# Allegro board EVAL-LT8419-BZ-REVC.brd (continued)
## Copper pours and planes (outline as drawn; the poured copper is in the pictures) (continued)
_N195 on TOP: 103.75,84.71 107.33,84.71 107.33,81.13 103.75,81.13
_N195 on TOP: 105.74,78.68 105.74,79.84 103.45,79.84 103.45,78.68
_N195 on TOP: 88.77,70.12 114.65,70.12 114.65,62.07 88.77,62.07
_N195 on TOP, BOTTOM: 107.09,76.98 107.09,77.68 103.49,77.68 103.49,76.98
_N195 on TOP, BOTTOM: 107.09,75.28 107.09,75.98 103.49,75.98 103.49,75.28
_N195 on TOP, BOTTOM: 98.1,77.83 98.1,78.53 94.5,78.53 94.5,77.83
_N195 on TOP, BOTTOM: 98.1,73.97 98.1,75.13 94.5,75.13 94.5,73.97
_N195 on TOP, BOTTOM: 98.1,76.13 98.1,76.83 94.5,76.83 94.5,76.13
_N195 on BOTTOM: 105.83,78.68 105.83,79.84 103.45,79.84 103.45,78.68
_N195 on BOTTOM: 114.65,70.17 114.65,62.07 88.77,62.07 88.77,65.99 98.59,65.99 99.14,66.53 99.14,67.41 99,67.54 98.43,67.54 98.27,67.38 98.27,67.02 98.21,66.97 88.77,66.97 88.77,70.17
_N195 on L2_PWR: 105.84,78.68 105.84,80.25 102.08,80.25 102.08,78.56 103.1,78.56 103.14,78.65 103.23,78.68
_N195 on L2_PWR: 102.44,80.25 103.1,80.25 103.1,71.01 114.65,71.01 114.65,62.07 88.77,62.07 88.77,71.01 95.91,71.01 95.91,73.97 98.61,73.97 98.61,78.25 100.79,78.25 100.79,84.09 102.44,84.09
_N195 on L2_PWR, L3_PWR, L4_PWR: 107.09,76.98 107.09,77.68 103.23,77.68 103.14,77.71 103.1,77.8 102.08,77.8 102.08,76.85 103.1,76.85 103.14,76.94 103.23,76.98
_N195 on L2_PWR, L3_PWR, L4_PWR: 107.09,75.28 107.09,75.98 103.23,75.98 103.14,76.01 103.1,76.1 102.08,76.1 102.08,75.15 103.1,75.15 103.14,75.24 103.23,75.28
_N195 on L2_PWR, L3_PWR, L4_PWR: 99.15,73.92 99.15,75.25 98.61,75.25 98.57,75.16 98.48,75.13 94.5,75.13 94.5,73.92
_N195 on L2_PWR, L3_PWR, L4_PWR: 99.19,76.95 98.61,76.95 98.57,76.86 98.48,76.83 94.5,76.83 94.5,76.13 98.48,76.13 98.57,76.09 98.61,76 99.19,76
_N195 on L2_PWR, L3_PWR, L4_PWR: 100.79,78.53 94.5,78.53 94.5,77.83 98.48,77.83 98.57,77.79 98.61,77.7 100.79,77.7
_N195 on L3_PWR: 105.74,78.68 105.74,80.25 102.08,80.25 102.08,78.56 103.1,78.56 103.14,78.65 103.23,78.68
_N195 on L3_PWR: 100.79,80.25 103.1,80.25 103.1,71.01 114.65,71.01 114.65,62.07 88.77,62.07 88.77,71.01 95.91,71.01 95.91,73.97 98.61,73.97 98.61,78.25 100.79,78.25
_N195 on L4_PWR: 100.79,79.84 103.1,79.84 103.1,71.01 114.65,71.01 114.65,62.07 88.77,62.07 88.77,71.01 95.91,71.01 95.91,73.97 98.61,73.97 98.61,78.25 100.79,78.25
_N195 on L4_PWR: 102.08,79.84 105.74,79.84 105.74,78.68 103.23,78.68 103.14,78.65 103.1,78.56 102.08,78.56
_N196 on BOTTOM: 88.77,61.56 88.77,54.92 114.65,54.92 114.65,61.56
_N196 on L2_PWR: 88.77,61.56 88.77,54.92 107.63,54.98 114.63,54.97 114.64,61.56
_N196 on L3_PWR: 88.77,61.56 88.77,54.92 114.65,54.92 114.65,61.56
_N196 on L4_PWR: 88.77,61.56 88.77,54.92 107.04,54.9 112.76,60.63 112.77,61.58
_N205 on TOP: 127.6,83.85 127.6,85.57 128.23,85.57 128.23,83.85
_N206 on TOP: 130.26,84.51 130.26,85.15 128.61,85.15 128.61,84.51
_N207 on TOP: 132.24,84.51 132.24,85.15 130.52,85.15 130.52,84.51
_N211 on TOP: 132.7,84.71 136.28,84.71 136.28,81.13 132.7,81.13
_N211 on TOP: 122.07,70.12 146.86,70.12 146.86,62.07 122.07,62.07
_N211 on TOP: 134.69,78.68 134.69,79.84 132.4,79.84 132.4,78.68
_N211 on TOP, BOTTOM: 127.05,77.83 127.05,78.53 123.45,78.53 123.45,77.83
_N211 on TOP, BOTTOM: 127.05,73.97 127.05,75.13 123.45,75.13 123.45,73.97
_N211 on TOP, BOTTOM: 127.05,76.13 127.05,76.83 123.45,76.83 123.45,76.13
_N211 on TOP, BOTTOM: 136.04,76.98 136.04,77.68 132.44,77.68 132.44,76.98
_N211 on TOP, BOTTOM: 136.04,75.28 136.04,75.98 132.44,75.98 132.44,75.28
_N211 on BOTTOM: 134.76,78.68 134.76,79.84 132.4,79.84 132.4,78.68
_N211 on BOTTOM: 143.6,70.17 143.6,62.07 122.07,62.07 122.07,65.69 130.83,65.69 131.26,66.11 131.26,67.28 131.15,67.39 130.59,67.39 130.42,67.23 130.42,66.81 130.27,66.66 122.07,66.66 122.07,70.17
_N211 on L2_PWR: 131.39,80.25 132.05,80.25 132.05,71.01 146.75,71.01 146.75,62.07 122.07,62.07 122.07,71.01 124.86,71.01 124.86,73.97 127.56,73.97 127.56,78.25 129.74,78.25 129.74,84.09 131.39,84.09
_N211 on L2_PWR: 134.77,78.68 134.77,80.25 131.03,80.25 131.03,78.56 132.05,78.56 132.09,78.65 132.18,78.68
_N211 on L2_PWR, L3_PWR, L4_PWR: 136.04,75.28 136.04,75.98 132.18,75.98 132.09,76.01 132.05,76.1 131.03,76.1 131.03,75.15 132.05,75.15 132.09,75.24 132.18,75.28
_N211 on L2_PWR, L3_PWR, L4_PWR: 129.74,78.53 123.45,78.53 123.45,77.83 127.43,77.83 127.52,77.79 127.56,77.7 129.74,77.7
_N211 on L2_PWR, L3_PWR, L4_PWR: 128.14,76.95 127.56,76.95 127.52,76.86 127.43,76.83 123.45,76.83 123.45,76.13 127.43,76.13 127.52,76.09 127.56,76 128.14,76
_N211 on L2_PWR, L3_PWR, L4_PWR: 128.11,73.92 128.11,75.25 127.56,75.25 127.52,75.16 127.43,75.13 123.45,75.13 123.45,73.92
_N211 on L2_PWR, L3_PWR, L4_PWR: 136.04,76.98 136.04,77.68 132.18,77.68 132.09,77.71 132.05,77.8 131.03,77.8 131.03,76.85 132.05,76.85 132.09,76.94 132.18,76.98
_N211 on L3_PWR: 134.69,78.68 134.69,80.25 131.03,80.25 131.03,78.56 132.05,78.56 132.09,78.65 132.18,78.68
_N211 on L3_PWR: 129.74,80.25 132.05,80.25 132.05,71.01 146.75,71.01 146.75,62.07 122.07,62.07 122.07,71.01 124.86,71.01 124.86,73.97 127.56,73.97 127.56,78.25 129.74,78.25
_N211 on L4_PWR: 131.03,79.84 134.69,79.84 134.69,78.68 132.18,78.68 132.09,78.65 132.05,78.56 131.03,78.56
_N211 on L4_PWR: 129.74,79.84 132.05,79.84 132.05,71.01 146.75,71.01 146.75,62.07 122.07,62.07 122.07,71.01 124.86,71.01 124.86,73.97 127.56,73.97 127.56,78.25 129.74,78.25
_N212 on BOTTOM: 122.07,61.56 122.07,54.92 143.6,54.92 143.6,61.56
_N212 on L2_PWR, L3_PWR: 122.07,61.56 122.07,54.92 146.65,54.92 146.65,61.56
_N212 on L4_PWR: 122.18,61.56 122.19,60.58 129.57,54.89 146.75,54.92 146.75,61.56
_N213 on TOP: 163.16,83.85 163.16,85.57 163.8,85.57 163.8,83.85
_N214 on TOP: 165.83,84.51 165.83,85.15 164.18,85.15 164.18,84.51
_N215 on TOP: 167.81,84.51 167.81,85.15 166.08,85.15 166.08,84.51
_N219 on TOP: 170.26,78.68 170.26,79.84 167.97,79.84 167.97,78.68
_N219 on TOP: 168.27,84.71 171.85,84.71 171.85,81.13 168.27,81.13
_N219 on TOP: 157.64,70.12 179.24,70.12 179.24,62.07 157.64,62.07
_N219 on TOP, BOTTOM: 162.62,73.97 162.62,75.13 159.02,75.13 159.02,73.97
_N219 on TOP, BOTTOM: 162.62,76.13 162.62,76.83 159.02,76.83 159.02,76.13
_N219 on TOP, BOTTOM: 171.6,75.28 171.6,75.98 168,75.98 168,75.28
_N219 on TOP, BOTTOM: 162.62,77.83 162.62,78.53 159.02,78.53 159.02,77.83
_N219 on TOP, BOTTOM: 171.6,76.98 171.6,77.68 168,77.68 168,76.98
_N219 on BOTTOM: 179.16,70.17 179.16,62.07 157.64,62.07 157.64,65.69 165.49,65.69 165.8,66 165.8,67.47 165.64,67.64 165.09,67.64 164.86,67.41 164.86,66.72 164.75,66.62 157.64,66.62 157.64,70.17
_N219 on BOTTOM: 170.35,78.68 170.35,79.84 167.97,79.84 167.97,78.68
_N219 on L2_PWR: 170.38,78.68 170.38,80.25 166.59,80.25 166.59,78.56 167.62,78.56 167.66,78.65 167.75,78.68
_N219 on L2_PWR: 166.95,80.25 167.62,80.25 167.62,71.01 179.16,71.01 179.16,62.07 157.64,62.07 157.64,71.01 160.43,71.01 160.43,73.97 163.12,73.97 163.12,78.25 165.31,78.25 165.31,84.09 166.95,84.09
_N219 on L2_PWR, L3_PWR, L4_PWR: 171.6,75.28 171.6,75.98 167.75,75.98 167.66,76.01 167.62,76.1 166.59,76.1 166.59,75.15 167.62,75.15 167.66,75.24 167.75,75.28
_N219 on L2_PWR, L3_PWR, L4_PWR: 163.71,76.95 163.12,76.95 163.09,76.86 163,76.83 159.02,76.83 159.02,76.13 163,76.13 163.09,76.09 163.12,76 163.71,76
_N219 on L2_PWR, L3_PWR, L4_PWR: 165.31,78.53 159.02,78.53 159.02,77.83 163,77.83 163.09,77.79 163.12,77.7 165.31,77.7
_N219 on L2_PWR, L3_PWR, L4_PWR: 171.6,76.98 171.6,77.68 167.75,77.68 167.66,77.71 167.62,77.8 166.59,77.8 166.59,76.85 167.62,76.85 167.66,76.94 167.75,76.98
_N219 on L2_PWR, L3_PWR, L4_PWR: 163.67,73.92 163.67,75.25 163.12,75.25 163.09,75.16 163,75.13 159.02,75.13 159.02,73.92
_N219 on L3_PWR: 170.26,78.68 170.26,80.25 166.59,80.25 166.59,78.56 167.62,78.56 167.66,78.65 167.75,78.68
_N219 on L3_PWR: 165.31,80.25 167.62,80.25 167.62,71.01 179.16,71.01 179.16,62.07 157.64,62.07 157.64,71.01 160.43,71.01 160.43,73.97 163.12,73.97 163.12,78.25 165.31,78.25
_N219 on L4_PWR: 165.31,79.84 167.62,79.84 167.62,71.01 179.16,71.01 179.16,62.07 157.64,62.07 157.64,71.01 160.43,71.01 160.43,73.97 163.12,73.97 163.12,78.25 165.31,78.25
_N219 on L4_PWR: 166.59,79.84 170.26,79.84 170.26,78.68 167.75,78.68 167.66,78.65 167.62,78.56 166.59,78.56
_N220 on BOTTOM: 157.64,61.56 157.64,54.92 179.16,54.92 179.16,61.56
_N220 on L2_PWR, L3_PWR, L4_PWR: 157.64,61.56 157.64,54.92 179.16,54.92 179.16,61.56
_N221 on TOP: 192.11,83.85 192.11,85.57 192.75,85.57 192.75,83.85
_N222 on TOP: 194.78,84.51 194.78,85.15 193.13,85.15 193.13,84.51
_N223 on TOP: 196.76,84.51 196.76,85.15 195.03,85.15 195.03,84.51
_N227 on TOP: 197.22,84.71 200.8,84.71 200.8,81.13 197.22,81.13
_N227 on TOP: 199.21,78.68 199.21,79.84 196.92,79.84 196.92,78.68
_N227 on TOP: 186.59,70.12 208.19,70.12 208.19,62.07 186.59,62.07
_N227 on TOP, BOTTOM: 200.55,76.98 200.55,77.68 196.96,77.68 196.96,76.98
_N227 on TOP, BOTTOM: 191.57,76.13 191.57,76.83 187.97,76.83 187.97,76.13
_N227 on TOP, BOTTOM: 200.55,75.28 200.55,75.98 196.96,75.98 196.96,75.28
_N227 on TOP, BOTTOM: 191.57,77.83 191.57,78.53 187.97,78.53 187.97,77.83
_N227 on TOP, BOTTOM: 191.57,73.97 191.57,75.13 187.97,75.13 187.97,73.97
_N227 on BOTTOM: 208.11,70.17 208.11,62.07 186.59,62.07 186.59,66 195.55,66 195.87,66.33 195.87,67.05 195.77,67.16 195.12,67.16 195.02,67.05 195.02,67.05 194.94,66.97 186.59,66.97 186.59,70.17
_N227 on BOTTOM: 199.28,78.68 199.28,79.84 196.92,79.84 196.92,78.68
_N227 on L2_PWR: 199.31,78.68 199.31,80.25 195.54,80.25 195.54,78.56 196.57,78.56 196.61,78.65 196.7,78.68
_N227 on L2_PWR: 195.9,80.25 196.57,80.25 196.57,71.01 208.11,71.01 208.11,62.07 186.59,62.07 186.59,71.01 189.38,71.01 189.38,73.97 192.07,73.97 192.07,78.25 194.26,78.25 194.26,84.09 195.9,84.09
_N227 on L2_PWR, L3_PWR, L4_PWR: 192.66,76.95 192.07,76.95 192.04,76.86 191.95,76.83 187.97,76.83 187.97,76.13 191.95,76.13 192.04,76.09 192.07,76 192.66,76
_N227 on L2_PWR, L3_PWR, L4_PWR: 200.55,76.98 200.55,77.68 196.7,77.68 196.61,77.71 196.57,77.8 195.54,77.8 195.54,76.85 196.57,76.85 196.61,76.94 196.7,76.98
_N227 on L2_PWR, L3_PWR, L4_PWR: 192.62,73.92 192.62,75.25 192.07,75.25 192.04,75.16 191.95,75.13 187.97,75.13 187.97,73.92
_N227 on L2_PWR, L3_PWR, L4_PWR: 194.26,78.53 187.97,78.53 187.97,77.83 191.95,77.83 192.04,77.79 192.07,77.7 194.26,77.7
_N227 on L2_PWR, L3_PWR, L4_PWR: 200.55,75.28 200.55,75.98 196.7,75.98 196.61,76.01 196.57,76.1 195.54,76.1 195.54,75.15 196.57,75.15 196.61,75.24 196.7,75.28
_N227 on L3_PWR: 194.26,80.25 196.57,80.25 196.57,71.01 208.11,71.01 208.11,62.07 186.59,62.07 186.59,71.01 189.38,71.01 189.38,73.97 192.07,73.97 192.07,78.25 194.26,78.25
_N227 on L3_PWR: 199.21,78.68 199.21,80.25 195.54,80.25 195.54,78.56 196.57,78.56 196.61,78.65 196.7,78.68
_N227 on L4_PWR: 194.26,79.84 196.57,79.84 196.57,71.01 208.11,71.01 208.11,62.07 186.59,62.07 186.59,71.01 189.38,71.01 189.38,73.97 192.07,73.97 192.07,78.25 194.26,78.25
_N227 on L4_PWR: 195.54,79.84 199.21,79.84 199.21,78.68 196.7,78.68 196.61,78.65 196.57,78.56 195.54,78.56
_N228 on BOTTOM: 186.59,61.56 186.59,54.92 208.11,54.92 208.11,61.56
_N228 on L2_PWR, L3_PWR, L4_PWR: 186.59,61.56 186.59,54.92 208.11,54.92 208.11,61.56
_N375 on TOP: 42.66,78.68 42.66,79.84 41.51,79.84 41.51,78.68
_N376 on TOP: 33.67,78.81 33.67,79.96 32.52,79.96 32.52,78.81
_N377 on TOP: 71.61,78.68 71.61,79.84 70.46,79.84 70.46,78.68
_N378 on TOP: 62.62,78.81 62.62,79.96 61.47,79.96 61.47,78.81
_N379 on TOP: 107.17,78.68 107.17,79.84 106.02,79.84 106.02,78.68
_N380 on TOP: 98.19,78.81 98.19,79.96 97.04,79.96 97.04,78.81
_N381 on TOP: 136.13,78.68 136.13,79.84 134.98,79.84 134.98,78.68
_N382 on TOP: 127.14,78.81 127.14,79.96 125.99,79.96 125.99,78.81
_N383 on TOP: 171.69,78.68 171.69,79.84 170.54,79.84 170.54,78.68
_N384 on TOP: 162.7,78.81 162.7,79.96 161.55,79.96 161.55,78.81
_N385 on TOP: 200.64,78.68 200.64,79.84 199.49,79.84 199.49,78.68
_N386 on TOP: 191.65,78.81 191.65,79.96 190.5,79.96 190.5,78.81
CSB on BOTTOM: 3.49,15.56 3.49,14.03 4.48,14.03 4.48,15.56
DRVCC on TOP: 99.68,82.86 99.68,83.44 99.02,83.44 98.87,83.59 98.39,83.59 98.28,83.7 98.28,84.58 97.1,84.58 97.1,82.65 98.63,82.65 98.84,82.86
DRVCC on TOP: 128.63,82.86 128.63,83.44 127.97,83.44 127.82,83.59 127.34,83.59 127.23,83.7 127.23,84.58 126.05,84.58 126.05,82.65 127.59,82.65 127.79,82.86
DRVCC on TOP: 35.16,82.86 35.16,83.44 34.5,83.44 34.35,83.59 33.87,83.59 33.76,83.7 33.76,84.58 32.58,84.58 32.58,82.65 34.12,82.65 34.33,82.86
DRVCC on TOP: 164.19,82.86 164.19,83.44 163.53,83.44 163.38,83.59 162.91,83.59 162.8,83.7 162.8,84.58 161.61,84.58 161.61,82.65 163.15,82.65 163.36,82.86
DRVCC on TOP: 193.14,82.86 193.14,83.44 192.48,83.44 192.34,83.59 191.86,83.59 191.75,83.7 191.75,84.58 190.57,84.58 190.57,82.65 192.1,82.65 192.31,82.86
DRVCC on TOP: 105.16,33.6 105.16,34.77 106.9,34.77 106.9,33.6
DRVCC on TOP: 64.11,82.86 64.11,83.44 63.45,83.44 63.3,83.59 62.82,83.59 62.71,83.7 62.71,84.58 61.53,84.58 61.53,82.65 63.07,82.65 63.28,82.86
DRVCC on L7_SIG: 190.87,80.84 190.87,84.25 190.87,84.25 32.54,84.25 32.54,80.84
PGOOD on TOP: 108.64,46.54 108.64,47.33 107.23,47.33 107.23,46.54
PWMEN on L7_SIG: 196.54,84.76 196.54,87.3 38.26,87.3 38.26,84.76
SAC1 on TOP: 122.15,46.54 122.15,48.57 121.69,49.03 121.69,49.09 121.25,49.53 120.4,49.53 120.37,49.56 120.37,50.2 120.46,50.29 121.49,50.29 121.7,50.08 121.7,50.07 123.09,50.07 123.09,46.54
SAC2 on TOP: 114.53,46.54 114.53,50.07 115.93,50.07 116.12,50.27 117.13,50.27 117.26,50.13 117.26,49.59 117.17,49.49 116.38,49.49 115.93,49.04 115.93,49.03 115.47,48.57 115.47,46.54
SAC3 on TOP: 113.34,46.54 113.34,48.57 112.88,49.03 112.88,50.07 112.89,50.07 112.86,50.1 112.86,50.64 112.26,51.23 110.99,51.23 110.99,51.97 111.02,52 112.52,52 114.28,50.24 114.28,46.54
SAC4 on TOP: 114.91,30.14 114.91,28.11 114.46,27.65 114.46,26.61 114.5,26.61 114.48,26.58 114.48,26.21 113.97,25.7 112.66,25.7 112.51,25.55 112.51,24.76 112.62,24.65 115.09,24.65 115.85,25.42 115.85,30.14
SAC5 on TOP: 116.11,30.14 116.11,26.61 116.24,26.48 118.78,26.48 118.81,26.51 118.81,27.22 117.94,27.22 117.05,28.11 117.05,30.14
SAC6 on TOP: 123.73,30.14 123.73,28.11 122.81,27.19 122.71,27.19 122.7,27.2 121.93,27.2 121.9,27.18 121.9,26.43 121.91,26.43 122.91,26.43 123.09,26.61 124.67,26.61 124.67,30.14
SCL on BOTTOM: 5.06,15.56 5.06,14.03 6.05,14.03 6.05,15.56
SDA on BOTTOM: 8.2,15.56 8.2,14.03 9.19,14.03 9.19,15.56
SDO on BOTTOM: 6.63,15.56 6.63,14.03 7.62,14.03 7.62,15.56
SN1 on TOP: 130.4,28.94 130.4,27.76 131.39,27.76 131.39,28.94
SN1 on TOP: 124.23,44.48 124.23,46.09 125.01,46.09 125.01,44.48
SN1 on TOP: 116.13,46.54 116.13,48.78 116.44,49.08 118.31,49.08 118.31,48.14 117.32,48.14 117.07,47.89 117.07,46.54
SN1 on TOP: 123.07,30.14 123.07,27.91 122.76,27.6 120.91,27.6 120.91,28.54 121.9,28.54 122.13,28.77 122.13,30.14
SN1 on TOP: 20.39,1.27 20.39,16.37 115.01,16.37 115.01,1.27
SN1 on TOP: 117.71,30.14 117.71,27.91 118.01,27.6 119.89,27.6 119.89,28.54 118.9,28.54 118.65,28.79 118.65,30.14
SN1 on TOP: 101.91,38.95 101.91,40.36 102.9,40.36 103.29,39.96 104.04,39.96 104.04,38.95
SN1 on TOP: 121.49,46.54 121.49,48.78 121.18,49.08 119.33,49.08 119.33,48.14 120.32,48.14 120.55,47.92 120.55,46.54
SN1 on TOP: 114.25,30.14 114.25,27.91 113.95,27.6 112.07,27.6 112.07,28.54 113.06,28.54 113.31,28.79 113.31,30.14
SN1 on TOP: 112.68,46.54 112.68,48.78 112.37,49.08 110.49,49.08 110.49,48.14 111.48,48.14 111.74,47.89 111.74,46.54
SN1 on BOTTOM: 186.59,54.41 201.93,54.41 201.93,27.95 202.06,27.95 202.06,17.03 115.36,17.03 115.36,2.03 20.78,2.03 20.78,27.95 28.61,27.95 28.61,54.41 43.95,54.41 43.95,31.56 57.56,31.56 57.56,54.41 72.9,54.41 72.9,31.91 88.77,31.91 88.77,54.41 104.11,54.41 104.11,27.95 112.09,27.95 112.24,27.8 121.85,27.8 121.97,27.92 121.97,27.95 126.43,27.95 126.43,54.41 141.77,54.41 141.77,31.74 157.64,31.74 157.64,54.41 172.98,54.41 172.98,31.74 186.59,31.74
SN1 on BOTTOM: 217.87,72.3 217.87,73.7 218.66,73.7 218.66,72.3
SN1 on L2_PWR: 186.59,54.41 201.93,54.41 201.93,16.54 115.26,16.54 115.26,1.27 20.78,1.27 20.78,27.95 28.61,27.95 28.61,54.41 43.95,54.41 43.95,31.38 57.56,31.38 57.56,54.41 72.9,54.41 72.9,31.52 88.77,31.52 88.77,54.41 109.65,54.41 109.65,54.44 124.56,54.44 124.56,54.41 141.77,54.41 141.77,31.73 157.64,31.73 157.64,54.41 172.98,54.41 172.98,32.29 186.59,32.29
SN1 on L3_PWR: 186.59,54.41 201.93,54.41 201.93,17.21 115.31,17.21 115.31,2.03 20.78,2.03 20.78,27.95 28.61,27.95 28.61,54.41 43.95,54.41 43.95,32.15 57.56,32.15 57.56,54.41 72.9,54.41 72.9,32.15 88.77,32.15 88.77,54.41 109.65,54.41 109.65,54.3 124.56,54.3 124.56,54.41 141.77,54.41 141.77,32.36 157.64,32.36 157.64,54.41 172.98,54.41 172.98,32.22 186.59,32.22
SN1 on L4_PWR: 22.48,1.27 22.48,17.21 114.3,17.21 114.3,1.27
SN1 on L5_GND: 19.02,1.27 19.02,17.28 113.96,17.28 113.96,1.27
SN1 on L6_SIG: 20.71,1.27 20.71,16.93 113.61,16.93 113.61,1.27
VHIGH on TOP: 36.28,138.43 114.05,138.43 114.05,123.79 208.11,123.79 208.11,70.63 194.26,70.63 194.26,83.38 196.28,83.38 196.28,86.57 194.26,88.59 194.26,105.28 179.16,105.28 179.16,70.63 165.31,70.63 165.31,83.38 167.33,83.38 167.33,86.57 165.31,88.59 165.31,106.29 165.22,106.38 146.85,106.38 146.72,106.25 146.72,105.87 146.72,105.28 146.68,105.28 146.68,70.63 129.74,70.63 129.74,83.38 131.76,83.38 131.76,86.57 129.74,88.59 129.74,105.46 114.65,105.46 114.65,70.63 100.79,70.63 100.79,83.38 102.81,83.38 102.81,86.57 100.79,88.59 100.79,105.45 81.74,105.45 81.74,70.63 65.23,70.63 65.23,83.38 67.25,83.38 67.25,86.57 65.23,88.59 65.23,104.94 50.13,104.94 50.13,70.63 36.28,70.63 36.28,83.38 38.29,83.38 38.29,86.57 36.28,88.59 ; 6 cut-outs
VHIGH on TOP: 127.83,45.61 127.83,47.01 129.49,47.01 129.49,45.61
VHIGH on TOP: 127.78,39.87 127.78,41.26 131.69,41.26 131.69,40.36 129.98,40.36 129.49,39.87
VHIGH on TOP: 102.77,28.24 102.77,26.58 104.52,26.58 104.52,28.24
VHIGH on BOTTOM: 217.54,78.09 217.54,80 218.58,80 218.58,78.09
VHIGH on BOTTOM: 36.28,138.43 36.28,70.68 50.13,70.68 50.13,107.35 65.23,107.35 65.23,70.68 82.09,70.68 82.09,106.83 100.79,106.83 100.79,70.68 114.65,70.68 114.65,106.32 129.74,106.32 129.74,70.68 143.6,70.68 143.61,70.67 146.68,70.7 146.68,105.8 165.31,105.8 165.31,70.68 179.16,70.68 179.16,106.06 194.26,106.06 194.26,70.68 208.11,70.68 208.11,123.74 114.05,123.74 114.05,138.43
VHIGH on L2_PWR: 36.28,138.43 36.28,79.77 36.27,79.77 36.27,71.52 50.13,71.52 50.13,106.12 65.23,106.12 65.23,70.63 82.13,70.63 82.13,106.19 100.79,106.19 100.79,70.63 114.65,70.63 114.65,106.4 129.74,106.4 129.74,70.63 143.6,70.63 143.64,70.59 146.68,70.59 146.68,106.23 146.85,106.4 165.31,106.4 165.31,70.63 179.16,70.63 179.16,106.12 194.26,106.12 194.26,70.63 208.11,70.63 208.11,123.79 114.05,123.79 114.05,138.43
VHIGH on L3_PWR: 36.28,138.43 36.28,70.63 50.13,70.63 50.13,106.05 65.23,106.05 65.23,70.63 78.19,70.63 78.19,70.64 79.05,71.5 79.58,71.5 79.59,71.49 79.58,71.49 79.58,70.63 82.06,70.63 82.06,106.33 100.79,106.33 100.79,70.63 114.65,70.63 114.65,106.05 129.74,106.05 129.74,70.63 143.6,70.63 143.6,71.54 143.62,71.52 146.69,71.52 146.69,106.12 165.31,106.12 165.31,70.63 179.16,70.63 179.16,105.84 194.26,105.84 194.26,70.63 208.11,70.63 208.11,123.93 114.05,123.93 114.05,138.43
VHIGH on L4_PWR: 36.28,138.43 36.28,70.63 50.13,70.63 50.13,106.19 65.23,106.19 65.23,70.63 78.84,70.63 78.84,71.3 79.04,71.51 79.56,71.51 79.59,71.49 79.59,70.65 79.6,70.63 82.05,70.63 82.06,70.65 82.06,106.26 100.79,106.26 100.79,70.63 114.65,70.63 114.65,105.91 129.74,105.91 129.74,70.63 143.6,70.63 143.6,71.52 146.68,71.52 146.69,71.53 146.69,106.26 165.31,106.26 165.31,70.63 179.16,70.63 179.16,106.12 194.26,106.12 194.26,70.63 208.11,70.63 208.11,123.93 114.05,123.93 114.05,138.43
VHIGH on L5_GND: 34.24,138.43 34.24,124 113.54,124 113.54,138.43
VHIGH on L6_SIG: 35.43,138.43 35.43,124.21 115.22,124.21 115.22,138.43

Small or netless copper shapes (teardrops, artwork), in the pictures only: 2 on TOP

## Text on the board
Ref Des/Silkscreen Bottom: IDENTIFY EEPROM | 08-087189 REV C | SECONDARY SIDE
User.Comments: 8-LAYER STACK-UP | L7 SIG | 08-      -12 | L6 SIG | 08-      -11 | L5 GND | 08-      -10 | L4 PWR | 08-      -09 | (10 PLACES) | SEE NOTE 6 | (20 PLACES) | SEE DETAIL A | 6.    INSTALL RING LUG: M048369 (MFG PN: 8205), WASHER: M000140 | (MFG PN: 98438A230), AND NUT: M069690 (MFG PN:  92671A195). | DIRECTIVE 2002/95/EC). | 3.    REPAIRS ARE NOT ALLOWED IN SOLDERMASK FREE AREAS ON EITHER | SIDE OF THE BOARD. | 4.    RoHS COMPLIANCE: ASSEMBLY VENDOR SHOULD ASSURE COMPLIANCE | WITH LEAD-FREE AND RoHS PCB ASSEMBLY STANDARDS (EU RoHS | 5.    INSTALL SHUNT: M023139 (MFG PN: M22-1900005) ON: | JP3: PIN 3 AND PIN 4    JP1:PIN 1 AND PIN 2 | JP4: PIN 1 AND PIN 2    S1: PIN 1 + PIN 4 AND PIN 2 + PIN 5 | 2.    REPAIRS PER IPC-7711/21 (LATEST REVISION) ARE ALLOWED. | 1X RING LUG, 1X WASHER, 2X NUT PER PLACE.
Ref Des/Assembly Top: 1 | C | A | +
Ref Des/Silkscreen Top: 1 | GND SW | GND | BG | TG-SW | a | CSB | SDA | SGND | PWMEN | PGOOD | FAULT | EXTVCC | SDO | SCL | TO DC590B OR | LINDUINO DC2026C | YES | NO | EXTERNAL BIAS | FOR LTC7871 | FROM LINDUINO | BOOST: 48V | BUCK: 30V TO 70V | BUCK: 12V | BOOST: 10V TO 14V | VHIGH | VLOW | CLKOUT | PRIMARY SIDE | 08-087189 REV C | P.S. (BOOST) | BURST (BUCK) | P.S. | FCM | LIGHT LOAD MODE | BUCK | BOOST | NONE | OFF | ON | RUN PIN | UVLO CIRCUIT | BUCK/BOOST | RUN | SETCUR | IMON | SYNC | MODE | + | SUPPLY/CHARGER LTC7871 WITH GAN FET DRIVERS LT8419 | HIGH POWER POLY-PHASE BI-DIRECTIONAL | EVAL-LT8419-BZ
PAGE_OUTLINE: C | B | PER ECR-130229 | REVISION B | 23MAR26 | 18SEP25 | P. PHAM | CUSTOMER EVALUATION
DIMENSION: NON-PLATED: +/- 2 MILS | PLATED: +/- 3 MILS | UNLESS SPECIFIED | HOLE TOLERANCE | DIA MAX / SEE NOTE 20 | " " | (REF) | L2 PWR | 08-      -07 | -
BODY_CENTER: L3 PWR | 08-      -08
User.12: FAB NOTES REVISION: NOVEMBER 21 2022 | 8.   IMPEDANCE REQUIREMENTS: IF NO STACKUP IS DEFINED, THE VENDOR IS ALLOWED TO ADJUST THE DIELECTRIC | 13.  PLATING SPECIFICATION: | 1.   DIMENSIONS ARE IN INCHES (EXCEPT WHERE NOTED). | ALL DOCUMENTS & SPECIFICATIONS REFERRED TO BELOW SHOULD BE THE LATEST REVISIONS. | 2.  BOARD MATERIAL:(USE CHECKED ITEMS) | 3.   ALL LAMINATES & BONDING MATERIALS SHOULD BE SELECTED FROM IPC-4101 OR IPC-4103,(TG>170 DEGC TD>300 DEGC) | 4.   REFER TO IPC-6010 SERIES, CLASS 2 FOR FABRICATION. | 5.   REFER TO LAMINATION DIAGRAM FOR OVERALL BOARD THICKNESS, TOLERANCE APPLIES AFTER ALL LAMINATION AND PLATING | 6.   BOW & TWIST NOT TO EXCEED 0.0075 INCHES (0.75%) PER LINEAR INCH AND SHOULD BE MEASURED PER IPC-TM-650, METHOD 2.4.22. | 7.   ACCEPTABILITY PER ADI SPECIFICATION TST00115. | 9.   FILLET OPTIONS TO ENHANCE RELIABILITY AT PAD JUNCTIONS WHERE SPACING PERMITS. | 10.  THIEVING: | 11.  LAYER TO LAYER REGISTRATION SHALL BE WITHIN 0.003 INCHES. | 12.  DRILL SIZES ARE FINISHED HOLE SIZES. ALL HOLES SHALL BE LOCATED WITHIN 0.005 INCHES DTP,UNLESS SPECIFIED. | 14.  SURFACE FINISH: | 15.  SOLDERMASK: | 16.  APPLY SILKSCREEN TO BOTH SIDES USING A NON-CONDUCTIVE, EPOXY BASED INK PER ARTWORK. | (X) WHITE | ( ) OTHER | PROCESSES. FINISHED THICKNESS MEASURED FROM TOP COPPER TO BOTTOM COPPER. | (X)  ISOLA 370HR OR S1000-2 OR IT180 OR EQUIVALENT | ( )  ISOLA-FR408HR OR EQUIVALENT | ( )  ISOLA IS410 | ( )  MEGTRON 6 | ( )  NELCO-4000-13 | ( )  ROGERS 4350B | ( )  ROGERS 3003 | ( )  ARLON 85N | ( )  EM370D | ( )  OTHER ________________________ | ( ) FILLETS ALLOWED | (X) FILLETS NOT ALLOWED | ( ) VENDOR MAY ADD THIEVING TO COMPENSATE FOR LOW COPPER DENSITY AREAS MAINTAINING A MINIMUM | (X) VENDOR MAY NOT ADD THIEVING TO COMPENSATE FOR LOW COPPER DENSITY AREAS. | (X) LPI | ( ) OTHER_________ | COLOR | (X) GREEN | ( ) OTHER: | HINDER PROPER SOLDER WICKING. BARREL RELIEF ON SOLDERMASK ALLOWED IN UNFILLED VIA IN PAD HOLES. | (X) REFER TO LAMINATION DIAGRAM FOR FINISHED COPPER WEIGHT/THICKNESS REQUIRMENTS | (X) IMMERSION GOLD (ENIG) 1.58-3.94 MICRO INCHES OVER 118-236 MICRO INCHES MIN. OF ELECTROLESS NICKEL PER IPC-4552 | ( ) OSP (ORGANIC SOLDERABILITY PRESERVATIVE) | ( ) IMMERSION SILVER | ( ) SOFT WIRE BONDABLE GOLD 30-50 MICRO INCHES OF SOFT WIRE | ( ) EDGE CONNECTOR FINGERS ARE TO BE PLATED WITH 100 MICRO-INCHES(.0001") OF LOW STRESS | THICKNESS & TRACE WIDTHS TO MEET THE IMPEDANCE REQUIREMENT. IF SPECIFIED, THE VENDOR MUST | TRACE WIDTH & SPACING THAT IMPACT THE REQUIREMENTS MUST HAVE WRITTEN APPROVAL FROM ADI. | MINIMUM BARREL PLATING OF 0.001 INCHES. PLATED HOLES SHALL NOT BE ROUGH OR IRREGULAR SO AS TO | SOLDERMASK OVER BARE COPPER OR BARE GOLD (BOTH SIDES) TO MEET IPC-SM-840. | IF PRESENT,DO NOT MODIFY SOLDERMASK DEFINED PADS (MASK OPENINGS LESS THAN COPPER PAD) WITHOUT APPROVAL. | MEET THE REQUIREMENTS LISTED IN THE IMPEDANCE TABLE. ANY ADJUSTMENT MADE TO THE DEFINED STACKUP, | UL FLAMMABILITY RATING 94V-0. BOARD MATERIAL & CONSTRUCTION SHALL MEET THE REQUIREMENTS OF UL796/UL796F. | BONDABLE GOLD OVER 100-150 MICRO INCHES OF NICKEL | NICKEL UNDER 30 MICRO-INCHES (.00003') OF GOLD | 0.100 INCH CLEARANCE FROM ALL COPPER FEATURES, | THE STARTING COPPER WEIGHT/THICKNESS CAN VARY AS LONG AS THE FINISHED COPPER | WEIGHT/THICKNESS IS NOT LESS THAN THE SPECIFIED VALUE. | UNLESS OTHERWISE SPECIFIED | HOMOGENOUS MATERIALS IN THIS BOARD SHALL BE COMPLAINT WITH THE EU DIRECTIVE 2002/95/EC | WORKMANSHIP SHALL CONFORM TO IPC-A-600, CLASS 2. | 21.  INTENTIONAL SHORTS: | 17.  FINAL ELECTRICAL TEST TO BE PERFORMED USING PROVIDED IPC-D-356A NETLIST OR ODB++ FORMAT FILE. | 22.  PEMNUTS: | 23.  MANUFACTURER TO ETCH/STAMP WITH PERMANENT NON-CONDUCTIVE INK | ON SECONDARY SIDE UNLESS OTHERWISE SPECIFIED: | 18.  A TIME DOMAIN REFLECTOMETER REPORT (TDR) FOR EACH IMPEDANCE CONTROLLED LAYER & A CERTIFICATE | 19.  IF PRESENT, ALL BLIND/BURIED VIAS WITH AN ASPECT RATIO <1:1 TO BE PLATED SHUT WITH COPPER WHEN | 20.  FOR VIA FILL INFORMATION REFER TO DRILL CHART: | 24. PANELIZATION: | 25.  MINIMUM DESIGN LINE WIDTH IS .0067 INCHES. | 26.  MINIMUM DESIGN LINE SPACING IS .005 INCHES. | BOARDS TO BE SHIPPED IN ARRAY AND KEPT INTACT | PANEL TO BE SUBJECTED TO CUSTOMERS APPROVAL | PANEL SOLDER PASTE STENCIL GERBER TO BE PROVIDED TO ANALOG | IS ACCEPTABLE, ALL OTHER INSTANCES MUST BE REPORTED. | IF AN INTENTIONAL SHORT REPORT IS SUPPLIED AND DOES NOT MATCH THE FAB DATA THEN | THE PCB SHALL HAVE A VERIFICATION STAMP. | (X)  NON-CONDUCTIVE EPOXY FILL ALL DRILLED VIAS | ( )  COPPER FILL ALL 0.XXXX INCHES DRILLED VIAS | ( ) PEMNUTS TO BE INSTALLED BY FABRICATOR | ( ) PEMNUTS NOT TO BE INSTALLED BY FABRICATOR | (X) NOT APPLICABLE | USED AS VIA-IN-PAD OR AS A STACKED VIA. BLIND/BURIED VIAS WITH AN ASPECT RATIO >1:1 TO BE FILLED | A. UL CODE-FLAMMABILITY RATING FOR THOSE APPROVED MATERIALS(IF APPLICABLE) | B. DATE CODE | C. LOT NUMBER | D. MANUFACTURER LOGO | CAN'T BE PERFORMED BECAUSE THE TRACE LENGTH IS TOO SHORT ON THE OUTER LAYERS AT THE PIN ESCAPES | ADI APPROVAL IS REQUIRED. | OF COMPLIANCE SHALL BE PROVIDED BY VENDOR AT TIME OF SHIPMENT. INSTANCES WHERE TDR TESTING | WITH NON-CONDUCTIVE EPOXY. | NOTES: | TOOLING: | FINISH: | MATERIAL: | TESTING: | MISCELLANEOUS:
User.45: FIGURE | SIZE | 6.0 | 10.0 | 12.0 | 35.0 | 36.0 | 45.0 | 100.0 | 187.0 | 191.0 | 118.0 | PLATED | NON-PLATED | DRILL CHART: TOP to BOTTOM | ALL UNITS ARE IN MILS | QTY | 1368 | 490 | 2807 | 47 | 14 | 2 | 21 | 4 | 10 | 12 | TOLERANCE/NOTES
